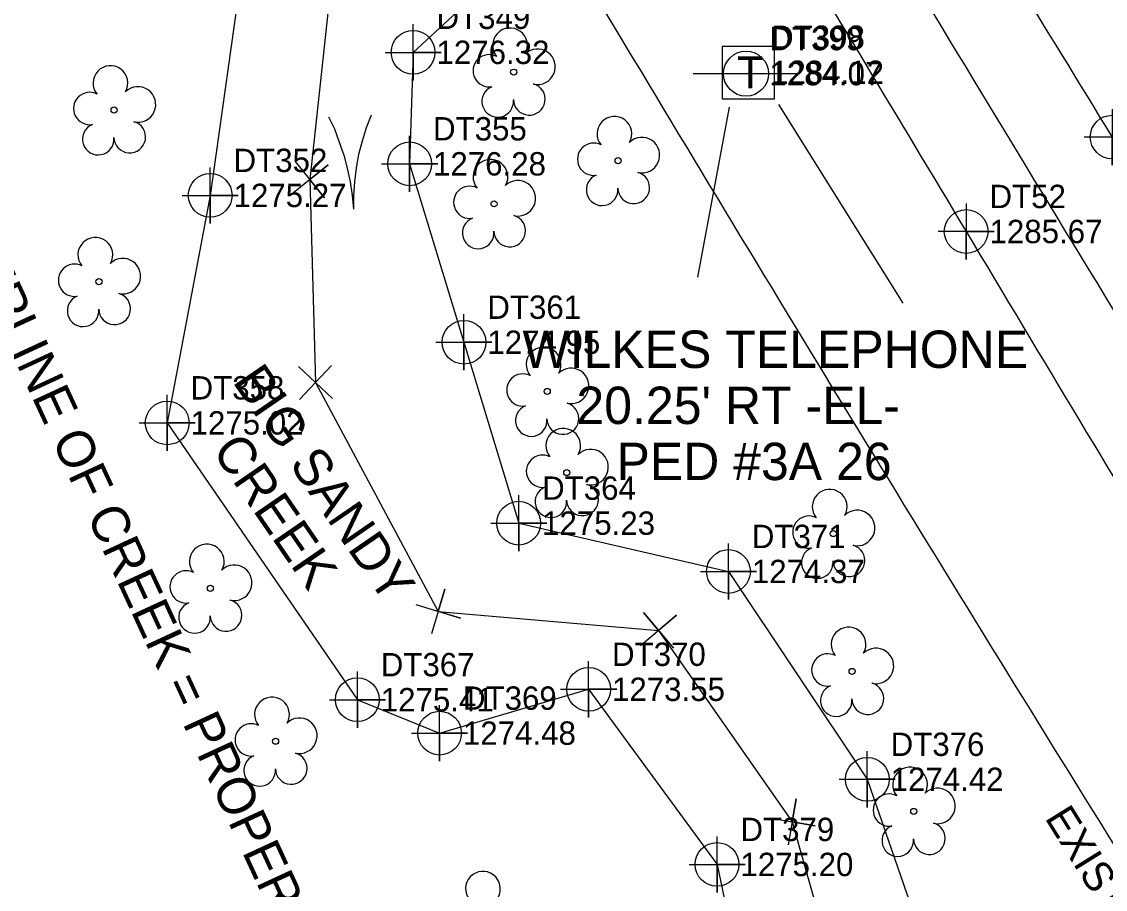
# Model space of a CAD drawing. Extents: x 1393723 to 1394549, y 957573 to 958412.
# Drawn here: x 1394136.3 to 1394252.2, y 957961.8 to 958054.6 of the extents above; entities that cross this region are included whole.
import ezdxf

# ---------------------------------------------------------------- set-up
doc = ezdxf.new("R2010")
doc.units = 0
for name, color, linetype in [('Exist Horizontal Alignment', 7, 'Continuous'), ('Exist Hydro Jurisdictional Stream or Body of Water', 7, 'Continuous'), ('Exist Hydro Jurisdictional Stream or Body of Water Text', 7, 'Continuous'), ('Exist Hydro Stream Flow Arrow CELL', 7, 'Continuous'), ('Exist Hydro Stream or Body of Water Cogo Elevation', 7, 'Continuous'), ('Exist Hydro Stream or Body of Water Cogo Number', 7, 'Continuous'), ('Exist Hydro Stream or Body of Water Cogo Point CELL', 7, 'Continuous'), ('Exist Property Corner CELL', 7, 'Continuous'), ('Exist Property Line', 7, 'Continuous'), ('Exist Property Line Text', 7, 'Continuous'), ('Exist Right of Way Line', 7, 'Continuous'), ('Exist Right of Way Line Text', 7, 'Continuous'), ('Exist Roads EOP', 7, 'Continuous'), ('Exist Roads EOP Cogo Elevation', 7, 'Continuous'), ('Exist Roads EOP Cogo Number', 7, 'Continuous'), ('Exist Roads EOP Cogo Point CELL', 7, 'Continuous'), ('Exist Utilities Telephone Pedestal CELL', 7, 'Continuous'), ('Exist Utilities Telephone Pedestal Cogo Elevation', 7, 'Continuous'), ('Exist Utilities Telephone Pedestal Cogo Number', 7, 'Continuous'), ('Exist Utilities Telephone Pole CELL', 7, 'Continuous'), ('Exist Utilities Telephone Pole Cogo Elevation', 7, 'Continuous'), ('Exist Utilities Telephone Pole Cogo Number', 7, 'Continuous'), ('Exist Utilities Telephone Pole Leader', 7, 'Continuous'), ('Exist Utilities Telephone Pole Text', 7, 'Continuous'), ('Exist Utilities Telephone UG FO', 7, 'Continuous'), ('Exist Vegetation Tree CELL', 7, 'Continuous')]:
    doc.layers.add(name, color=color, linetype=linetype)

msp = doc.modelspace()

# ---------------------------------------------------------------- linework, layer by layer
at = {"layer": 'Exist Horizontal Alignment'}
msp.add_arc((1399628.18, 961309.9), 6300, 210.988188, 211.917005, dxfattribs=at)
at = {"layer": 'Exist Hydro Jurisdictional Stream or Body of Water'}
for points in [[(1394193.9, 958099.87), (1394177.23, 958076.17), (1394160.33, 958063.43), (1394156.48, 958036.02), (1394151.88, 958011.68), (1394172.23, 957982.06), (1394181.02, 957978.48), (1394196.97, 957983.17), (1394210.71, 957964.43), (1394215.47, 957941.6), (1394209.55, 957917.15)], [(1394208.46, 958075.88), (1394187.58, 958060.01), (1394178.19, 958051.33), (1394177.82, 958039.4), (1394183.63, 958020.31), (1394189.49, 958000.95), (1394211.93, 957995.78), (1394226.78, 957973.54), (1394236.58, 957945.21), (1394231.94, 957908.56)]]:
    msp.add_lwpolyline(points, dxfattribs=at)
at = {"layer": 'Exist Hydro Stream Flow Arrow CELL'}
msp.add_line((1394171.6, 958039.53), (1394171.6, 958039.53), dxfattribs=at)
for points in [[(1394169.12, 958044.44), (1394169.77, 958043.13), (1394170.29, 958041.72), (1394170.78, 958040.33), (1394171.15, 958038.93), (1394171.45, 958037.48), (1394171.67, 958036), (1394171.8, 958034.54)], [(1394173.69, 958044.62), (1394173.15, 958043.26), (1394172.74, 958041.82), (1394172.36, 958040.39), (1394172.1, 958038.96), (1394171.92, 958037.49), (1394171.82, 958036), (1394171.8, 958034.54)]]:
    msp.add_lwpolyline(points, dxfattribs=at)
at = {"layer": 'Exist Hydro Stream or Body of Water Cogo Point CELL'}
for points in [[(1394175.19, 958051.33), (1394181.19, 958051.33), (1394178.19, 958051.33), (1394178.19, 958048.33), (1394178.19, 958054.33)], [(1394174.82, 958039.4), (1394180.82, 958039.4), (1394177.82, 958039.4), (1394177.82, 958036.4), (1394177.82, 958042.4)], [(1394153.48, 958036.02), (1394159.48, 958036.02), (1394156.48, 958036.02), (1394156.48, 958033.02), (1394156.48, 958039.02)], [(1394180.63, 958020.31), (1394186.63, 958020.31), (1394183.63, 958020.31), (1394183.63, 958017.31), (1394183.63, 958023.31)], [(1394148.88, 958011.68), (1394154.88, 958011.68), (1394151.88, 958011.68), (1394151.88, 958008.68), (1394151.88, 958014.68)], [(1394186.49, 958000.95), (1394192.49, 958000.95), (1394189.49, 958000.95), (1394189.49, 957997.95), (1394189.49, 958003.95)], [(1394208.93, 957995.78), (1394214.93, 957995.78), (1394211.93, 957995.78), (1394211.93, 957992.78), (1394211.93, 957998.78)], [(1394193.97, 957983.17), (1394199.97, 957983.17), (1394196.97, 957983.17), (1394196.97, 957980.17), (1394196.97, 957986.17)], [(1394169.23, 957982.06), (1394175.23, 957982.06), (1394172.23, 957982.06), (1394172.23, 957979.06), (1394172.23, 957985.06)], [(1394178.02, 957978.48), (1394184.02, 957978.48), (1394181.02, 957978.48), (1394181.02, 957975.48), (1394181.02, 957981.48)], [(1394223.78, 957973.54), (1394229.78, 957973.54), (1394226.78, 957973.54), (1394226.78, 957970.54), (1394226.78, 957976.54)], [(1394207.71, 957964.43), (1394213.71, 957964.43), (1394210.71, 957964.43), (1394210.71, 957961.43), (1394210.71, 957967.43)]]:
    msp.add_lwpolyline(points, dxfattribs=at)
for centre in [(1394178.19, 958051.33), (1394177.82, 958039.4), (1394156.48, 958036.02), (1394183.63, 958020.31), (1394151.88, 958011.68), (1394189.49, 958000.95), (1394211.93, 957995.78), (1394196.97, 957983.17), (1394172.23, 957982.06), (1394181.02, 957978.48), (1394226.78, 957973.54), (1394210.71, 957964.43)]:
    msp.add_circle(centre, 2.34, dxfattribs=at)
at = {"layer": 'Exist Property Corner CELL'}
for p, q in [((1394167.15, 958037.71), (1394167.15, 958037.71)), ((1394167.76, 958015.99), (1394167.76, 958015.99)), ((1394180.86, 957991.5), (1394180.86, 957991.5)), ((1394204.45, 957989.48), (1394204.45, 957989.48)), ((1394218.74, 957968.99), (1394218.74, 957968.99))]:
    msp.add_line(p, q, dxfattribs=at)
for points in [[(1394165.58, 958039.65), (1394168.72, 958035.76), (1394167.15, 958037.71), (1394169.1, 958039.28), (1394165.21, 958036.14)], [(1394165.94, 958017.71), (1394169.57, 958014.28), (1394167.76, 958015.99), (1394169.47, 958017.81), (1394166.04, 958014.18)], [(1394178.47, 957992.23), (1394183.26, 957990.78), (1394180.86, 957991.5), (1394181.59, 957993.9), (1394180.14, 957989.11)], [(1394202.53, 957987.87), (1394206.36, 957991.09), (1394204.45, 957989.48), (1394202.84, 957991.39), (1394206.06, 957987.56)], [(1394216.28, 957969.42), (1394221.21, 957968.55), (1394218.74, 957968.99), (1394219.18, 957971.45), (1394218.31, 957966.53)]]:
    msp.add_lwpolyline(points, dxfattribs=at)
at = {"layer": 'Exist Property Line'}
for p, q in [((1394169.26, 958057.38), (1394167.15, 958037.71)), ((1394167.15, 958037.71), (1394167.76, 958015.99)), ((1394167.76, 958015.99), (1394180.86, 957991.5)), ((1394180.86, 957991.5), (1394204.45, 957989.48)), ((1394204.45, 957989.48), (1394218.74, 957968.99)), ((1394218.74, 957968.99), (1394226.02, 957943.4))]:
    msp.add_line(p, q, dxfattribs=at)
at = {"layer": 'Exist Right of Way Line'}
msp.add_line((1394157.44, 958124.42), (1394201.64, 958050.83), dxfattribs=at)
msp.add_arc((1399628.18, 961309.9), 6330, 210.988188, 211.917005, dxfattribs=at)
at = {"layer": 'Exist Roads EOP'}
for points in [[(1394231.47, 958077.14), (1394252.98, 958042.26), (1394277.17, 958002.55), (1394302.35, 957962.17), (1394325.75, 957924.49)], [(1394215.84, 958067.9), (1394237.36, 958032.16), (1394261.7, 957991.75), (1394286.48, 957951.93), (1394310.18, 957914.04)]]:
    msp.add_spline(points, degree=3, dxfattribs=at)
at = {"layer": 'Exist Roads EOP Cogo Point CELL'}
for points in [[(1394252.98, 958045.26), (1394252.98, 958039.26), (1394252.98, 958042.26), (1394255.98, 958042.26), (1394249.98, 958042.26)], [(1394237.36, 958035.16), (1394237.36, 958029.16), (1394237.36, 958032.16), (1394240.36, 958032.16), (1394234.36, 958032.16)]]:
    msp.add_lwpolyline(points, dxfattribs=at)
for centre in [(1394252.98, 958042.26), (1394237.36, 958032.16)]:
    msp.add_circle(centre, 2.34, dxfattribs=at)
at = {"layer": 'Exist Utilities Telephone Pedestal CELL'}
msp.add_line((1394213.99, 958049.2), (1394213.99, 958049.2), dxfattribs=at)
msp.add_lwpolyline([(1394211.26, 958046.37), (1394216.86, 958046.37), (1394216.86, 958051.96), (1394211.26, 958051.96), (1394211.26, 958046.37)], dxfattribs=at)
at = {"layer": 'Exist Utilities Telephone Pole CELL'}
for p, q in [((1394208.14, 958049.05), (1394219.48, 958049.05)), ((1394213.81, 958049.05), (1394213.81, 958049.05))]:
    msp.add_line(p, q, dxfattribs=at)
msp.add_circle((1394213.81, 958049.05), 2.41, dxfattribs=at)
at = {"layer": 'Exist Utilities Telephone Pole Leader'}
msp.add_lwpolyline([(1394212.01, 958045.47), (1394208.61, 958027.27)], dxfattribs=at)
at = {"layer": 'Exist Utilities Telephone UG FO'}
msp.add_lwpolyline([(1394217.27, 958045.76), (1394230.58, 958024.48)], dxfattribs=at)
at = {"layer": 'Exist Vegetation Tree CELL'}
for p, q in [((1394188.95, 958049.21), (1394188.95, 958049.21)), ((1394146.2, 958045.16), (1394146.2, 958045.16)), ((1394200.12, 958039.74), (1394200.12, 958039.74)), ((1394186.85, 958035.12), (1394186.85, 958035.12)), ((1394144.58, 958026.79), (1394144.58, 958026.79)), ((1394192.54, 958015.05), (1394192.54, 958015.05)), ((1394194.63, 958006.36), (1394194.63, 958006.36)), ((1394223.15, 957999.84), (1394223.15, 957999.84)), ((1394156.5, 957993.98), (1394156.5, 957993.98)), ((1394225.16, 957985.08), (1394225.16, 957985.08)), ((1394163.47, 957977.61), (1394163.47, 957977.61)), ((1394231.75, 957970.1), (1394231.75, 957970.1))]:
    msp.add_line(p, q, dxfattribs=at)
for centre in [(1394188.95, 958049.21), (1394146.2, 958045.16), (1394200.12, 958039.74), (1394186.85, 958035.12), (1394144.58, 958026.79), (1394192.54, 958015.05), (1394194.63, 958006.36), (1394223.15, 957999.84), (1394156.5, 957993.98), (1394225.16, 957985.08), (1394163.47, 957977.61), (1394231.75, 957970.1)]:
    msp.add_circle(centre, 0.326, dxfattribs=at)
for centre, radius, start, end in [((1394188.56, 958052.08), 1.86, 330.1651, 219.7134), ((1394186.34, 958049.36), 1.73, 62.6636, 279.3457), ((1394191.5, 958049.79), 1.9, 257.1011, 134.1999), ((1394145.81, 958048.04), 1.86, 330.1651, 219.7134), ((1394148.75, 958045.75), 1.9, 257.1011, 134.1999), ((1394187.24, 958046.08), 1.69, 111.5671, 6.231), ((1394190.62, 958046.31), 1.7, 181.2822, 74.56), ((1394143.59, 958045.32), 1.73, 62.6636, 279.3457), ((1394199.73, 958042.61), 1.86, 330.1651, 219.7134), ((1394144.5, 958042.04), 1.69, 111.5671, 6.231), ((1394147.87, 958042.27), 1.7, 181.2822, 74.56), ((1394202.67, 958040.33), 1.9, 257.1011, 134.1999), ((1394197.51, 958039.89), 1.73, 62.6636, 279.3457), ((1394186.47, 958038), 1.86, 330.1651, 219.7134), ((1394201.79, 958036.84), 1.7, 181.2822, 74.56), ((1394189.4, 958035.71), 1.9, 257.1011, 134.1999), ((1394198.41, 958036.62), 1.69, 111.5671, 6.231), ((1394184.25, 958035.28), 1.73, 62.6636, 279.3457), ((1394188.52, 958032.22), 1.7, 181.2822, 74.56), ((1394185.15, 958032), 1.69, 111.5671, 6.231), ((1394144.19, 958029.66), 1.86, 330.1651, 219.7134), ((1394147.13, 958027.38), 1.9, 257.1011, 134.1999), ((1394141.97, 958026.94), 1.73, 62.6636, 279.3457), ((1394146.25, 958023.89), 1.7, 181.2822, 74.56), ((1394142.88, 958023.67), 1.69, 111.5671, 6.231), ((1394192.15, 958017.92), 1.86, 330.1651, 219.7134), ((1394195.09, 958015.64), 1.9, 257.1011, 134.1999), ((1394189.93, 958015.2), 1.73, 62.6636, 279.3457), ((1394190.83, 958011.93), 1.69, 111.5671, 6.231), ((1394194.21, 958012.15), 1.7, 181.2822, 74.56), ((1394194.25, 958009.23), 1.86, 330.1651, 219.7134), ((1394192.03, 958006.51), 1.73, 62.6636, 279.3457), ((1394197.18, 958006.95), 1.9, 257.1011, 134.1999), ((1394192.93, 958003.24), 1.69, 111.5671, 6.231), ((1394196.31, 958003.46), 1.7, 181.2822, 74.56), ((1394222.76, 958002.71), 1.86, 330.1651, 219.7134), ((1394220.54, 957999.99), 1.73, 62.6636, 279.3457), ((1394225.7, 958000.43), 1.9, 257.1011, 134.1999), ((1394156.12, 957996.85), 1.86, 330.1651, 219.7134), ((1394221.44, 957996.72), 1.69, 111.5671, 6.231), ((1394224.82, 957996.94), 1.7, 181.2822, 74.56), ((1394153.9, 957994.13), 1.73, 62.6636, 279.3457), ((1394159.05, 957994.57), 1.9, 257.1011, 134.1999), ((1394154.8, 957990.86), 1.69, 111.5671, 6.231), ((1394158.17, 957991.08), 1.7, 181.2822, 74.56), ((1394224.78, 957987.96), 1.86, 330.1651, 219.7134), ((1394227.71, 957985.67), 1.9, 257.1011, 134.1999), ((1394222.56, 957985.24), 1.73, 62.6636, 279.3457), ((1394226.84, 957982.18), 1.7, 181.2822, 74.56), ((1394223.46, 957981.96), 1.69, 111.5671, 6.231), ((1394163.09, 957980.48), 1.86, 330.1651, 219.7134), ((1394160.87, 957977.76), 1.73, 62.6636, 279.3457), ((1394166.02, 957978.2), 1.9, 257.1011, 134.1999), ((1394161.77, 957974.49), 1.69, 111.5671, 6.231), ((1394165.15, 957974.71), 1.7, 181.2822, 74.56), ((1394231.36, 957972.97), 1.86, 330.1651, 219.7134), ((1394234.3, 957970.69), 1.9, 257.1011, 134.1999), ((1394229.14, 957970.25), 1.73, 62.6636, 279.3457), ((1394233.42, 957967.2), 1.7, 181.2822, 74.56), ((1394230.04, 957966.98), 1.69, 111.5671, 6.231), ((1394185.66, 957961.83), 1.86, 330.1651, 219.7134)]:
    msp.add_arc(centre, radius, start, end, dxfattribs=at)

# ---------------------------------------------------------------- texts
at = {"layer": 'Exist Hydro Jurisdictional Stream or Body of Water Text'}
for s, p in [('BIG SANDY', (1394158.8, 958016.11)), (' CREEK', (1394155.75, 958009.95))]:
    msp.add_text(s, height=4, rotation=304.4933, dxfattribs=at).set_placement(p)
at = {"layer": 'Exist Hydro Stream or Body of Water Cogo Elevation'}
for s, p in [('1276.32', (1394180.69, 958050.08)), ('1276.28', (1394180.32, 958038.15)), ('1275.27', (1394158.98, 958034.77)), ('1274.95', (1394186.13, 958019.06)), ('1275.02', (1394154.38, 958010.43)), ('1275.23', (1394191.99, 957999.7)), ('1274.37', (1394214.43, 957994.53)), ('1273.55', (1394199.47, 957981.92)), ('1275.41', (1394174.73, 957980.81)), ('1274.48', (1394183.52, 957977.23)), ('1274.42', (1394229.28, 957972.29)), ('1275.20', (1394213.21, 957963.18))]:
    msp.add_text(s, height=2.5, dxfattribs=at).set_placement(p)
at = {"layer": 'Exist Hydro Stream or Body of Water Cogo Number'}
for s, p in [('DT349', (1394180.69, 958053.83)), ('DT355', (1394180.32, 958041.9)), ('DT352', (1394158.98, 958038.52)), ('DT361', (1394186.13, 958022.81)), ('DT358', (1394154.38, 958014.18)), ('DT364', (1394191.99, 958003.45)), ('DT371', (1394214.43, 957998.28)), ('DT370', (1394199.47, 957985.67)), ('DT367', (1394174.73, 957984.56)), ('DT369', (1394183.52, 957980.98)), ('DT376', (1394229.28, 957976.04)), ('DT379', (1394213.21, 957966.93))]:
    msp.add_text(s, height=2.5, dxfattribs=at).set_placement(p)
at = {"layer": 'Exist Property Line Text'}
msp.add_text('CENTERLINE OF CREEK = PROPERTY LINE', height=4, rotation=294.7971, dxfattribs=at).set_placement((1394124.63, 958042.03))
at = {"layer": 'Exist Right of Way Line Text'}
msp.add_text('EXISTING R/W', height=3.2, rotation=301.917, dxfattribs=at).set_placement((1394245.72, 957969.4))
at = {"layer": 'Exist Roads EOP Cogo Elevation'}
msp.add_text('1285.67', height=2.5, dxfattribs=at).set_placement((1394239.86, 958030.91))
at = {"layer": 'Exist Roads EOP Cogo Number'}
msp.add_text('DT52', height=2.5, dxfattribs=at).set_placement((1394239.86, 958034.66))
at = {"layer": 'Exist Utilities Telephone Pedestal CELL'}
msp.add_text('T', height=3.42, dxfattribs=at).set_placement((1394212.86, 958047.48))
at = {"layer": 'Exist Utilities Telephone Pedestal Cogo Elevation'}
msp.add_text('1284.12', height=2.5, dxfattribs=at).set_placement((1394216.49, 958047.95))
at = {"layer": 'Exist Utilities Telephone Pedestal Cogo Number'}
msp.add_text('DT398', height=2.5, dxfattribs=at).set_placement((1394216.49, 958051.7))
at = {"layer": 'Exist Utilities Telephone Pole Cogo Elevation'}
msp.add_text('1284.07', height=2.5, dxfattribs=at).set_placement((1394216.31, 958047.8))
at = {"layer": 'Exist Utilities Telephone Pole Cogo Number'}
msp.add_text('DT399', height=2.5, dxfattribs=at).set_placement((1394216.31, 958051.55))
at = {"layer": 'Exist Utilities Telephone Pole Text'}
for s, p in [('WILKES TELEPHONE', (1394189.89, 958017.56)), ("20.25' RT -EL-", (1394195.66, 958011.56)), ('PED #3A 26', (1394199.95, 958005.56))]:
    msp.add_text(s, height=4, rotation=359.9944, dxfattribs=at).set_placement(p)

doc.saveas('drawing.dxf')
